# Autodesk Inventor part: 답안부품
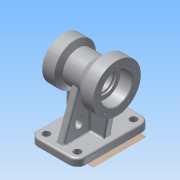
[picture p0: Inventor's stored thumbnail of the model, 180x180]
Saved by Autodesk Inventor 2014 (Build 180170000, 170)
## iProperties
Created: 2015-08
Part Number: 답안부품
Material: 알루미늄 6061
Document SubType Name: Modeling
Designer: sda20
Density: 2.71 g/cm^3
Appearance: 알루미늄 - 평지
Mass: 1067.5 g
Surface Area: 774.349 cm^2
Volume: 393.91 cm^3
Author: sda20
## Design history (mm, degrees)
sketch "스케치9"
  geometry: C1 r 26 at (0, 0); 1 further point
  constraints: 1 centre point, 1 coincident
  dimensions: "d93" = 52 diameter of C1
extrude "돌출4" new body sketch "스케치9" stored distance "d94" = 50; taper "d95" = 0 deg
sketch "스케치10"
  geometry: C1 r 26 at (0, 0) reference; C2 r 35 at (0, 0)
  constraints: 1 centre point, 1 coincident
  dimensions: "d96" = 70 diameter of C2
extrude "돌출5" join sketch "스케치10" distance "d97" = 20; taper "d98" = 0 deg
sketch "스케치11"
  geometry: C1 r 26 at (0, 0) reference; C2 r 40 at (0, 0)
  constraints: 1 centre point, 1 coincident
  dimensions: "d99" = 80 diameter of C2
extrude "돌출6" join sketch "스케치11" distance "d100" = 20; taper "d101" = 0 deg
sketch "스케치12"
  geometry: L1 (-35, 25)-(35, 25) reference; L2 (35, 45)-(-35, 45) reference; L3 (0, 45)-(0, -45); L4 (-40, -45)-(40, -45) reference; L5 (35, 25)-(26, 19.804); L6 (26, -25)-(26, 25) reference; L7 (40, -25)-(-40, -25) reference; L8 (40, -25)-(26, -8.315); 1 further point
  constraints: 7 end point, 2 midpoint, 2 point on line, 1 perpendicular
  dimensions: "d102" = 60 deg angle of L6 L5; "d103" = 40 deg angle of L6 L8
revolve "회전3" sketch "스케치12" stored, may be unused: angle "d104" = 90 deg
node "작업 평면4"
sketch "스케치13"
  geometry: L1 (61, 40)-(-61, 40); L2 (-61, 40)-(-61, -40); L3 (-61, -40)-(61, -40); L4 (61, -40)-(61, 40); L5 (61, 40)-(-61, -40); L6 (-61, 40)-(61, -40); 1 further point
  constraints: 12 end point, 2 midpoint, 2 parallel, 1 horizontal, 1 perpendicular
  dimensions: "d106" = 122 distance of L3.end L2.end; "d107" = 80 distance of L3.end L1.start
extrude "돌출7" join sketch "스케치13" distance "d108" = 12; taper "d109" = 0 deg
hole "구멍9" diameter "d122" = 52; stored, may be unused: countersink angle "d126" = 90 deg, drill point angle "d128" = 0 deg; dims "d120" = 10, "d121" = 10, "d123" = 6, "d124" = 4, "d125" = 2, "d127" = 20
hole "구멍10" diameter "d131" = 38; stored, may be unused: countersink angle "d135" = 90 deg, drill point angle "d137" = 0 deg; dims "d129" = 10, "d130" = 10, "d132" = 6, "d133" = 4, "d134" = 2, "d136" = 3
hole "구멍11" diameter "d140" = 40; stored, may be unused: countersink angle "d144" = 90 deg, drill point angle "d146" = 0 deg; dims "d138" = 10, "d139" = 10, "d141" = 6, "d142" = 4, "d143" = 2, "d145" = 17
hole "구멍12" diameter "d149" = 32; stored, may be unused: countersink angle "d153" = 90 deg, drill point angle "d155" = 0 deg; dims "d147" = 10, "d148" = 10, "d150" = 6, "d151" = 4, "d152" = 2, "d154" = 17
sketch "스케치18" dims "d156" = 54
  geometry: C1 r 20 at (0, 0) reference; C2 r 35 at (0, 0) reference; 2 further points
  constraints: 2 vertical alignment, 1 coincident, 2 other
hole "구멍13" sketch "스케치18" at (0, 27) diameter "d157" = 3.242; stored, may be unused: countersink angle "d161" = 90 deg, drill point angle "d163" = 118 deg; dims "d158" = 10, "d159" = 4, "d160" = 2, "d162" = 13
sketch "스케치19" dims "d167" = 66
  geometry: C1 r 26 at (0, 0) reference; C2 r 40 at (0, 0) reference; 2 further points
  constraints: 2 vertical alignment, 1 coincident, 2 other
hole "구멍14" sketch "스케치19" at (0, 33) diameter "d168" = 3.242; stored, may be unused: countersink angle "d172" = 90 deg, drill point angle "d174" = 118 deg; dims "d169" = 10, "d170" = 4, "d171" = 2, "d173" = 13
sketch "스케치23"
  geometry: L1 (25.091, -6.815)-(51, -78); L2 (-61, -78)-(61, -78) reference; L3 (61, -90)-(61, -78) reference; L4 (61, -78)-(-61, -78) reference; L5 (0, -78)-(0, -26); L6 (0, -78)-(51, -78); A1 r 26 centre (0, 0) between (0, -26) and (25.091, -6.815); 1 further point
  constraints: 6 end point, 2 point on circle, 1 centre point, 1 coincident, 1 collinear, 1 midpoint, 1 perpendicular, 1 point on line
  dimensions: "d185" = 10 distance from line of L3 L1.end; "d186" = 70 deg angle of L2 L1; "d192" = 26 radius of A1
extrude "돌출9" join sketch "스케치23" stored distance "d193" = 12; taper "d194" = 0 deg
sketch "스케치24"
  geometry: L1 (-35, 25)-(-35, 45) reference; L2 (-35, 25)-(-26, 19.804) reference; L3 (-26, -8.315)-(-26, 19.804) reference; L4 (-26, -8.315)-(-40, -25) reference; L5 (-40, -25)-(-40, -45) reference; L6 (-78, -40)-(-78, 40) reference; L7 (-40, -36.7)-(-78, -30); L8 (-90, -40)-(-78, -40) reference; L9 (-35, 35)-(-78, 35); 1 further point
  constraints: 4 end point, 3 point on line, 1 midpoint, 1 perpendicular
  dimensions: "d195" = 10 distance from line of L8 L7.end; "d196" = 80 deg angle of L6 L7
extrude "돌출10" join sketch "스케치24" stored distance "d197" = 12; taper "d198" = 0 deg
sketch "스케치25"
  geometry: 2 further points
  dimensions: "d199" = 47 horizontal distance of point (0, 0) point (-47, 26); "d200" = 26 vertical distance of point (0, 0) point (-47, 26)
hole "구멍15" sketch "스케치25" at (-47, 26) diameter "d201" = 12; stored, may be unused: countersink angle "d205" = 90 deg, drill point angle "d207" = 0 deg; dims "d202" = 12, "d203" = 4, "d204" = 2, "d206" = 13
sketch "스케치26"
  geometry: L1 (-6, -78)-(-51, -78) reference; L2 (-18, -54)-(-18, -60); L3 (-30, -54)-(-30, -60); A1 r 26 centre (0, 0) between (-25.091, -6.815) and (0, -26) reference; A2 r 6 centre (-24, -60) between (-30, -60) and (-18, -60); A3 r 6 centre (-24, -54) between (-18, -54) and (-30, -54); 2 further points
  constraints: 6 point on circle, 4 end point, 3 tangent, 3 vertical alignment, 2 centre point, 1 parallel
  dimensions: "d210" = 12 diameter of A2; "d211" = 18 distance from line of L1 A2.centre; "d212" = 24 horizontal distance of A1.centre A2.centre; "d213" = 12 diameter of A3; "d214" = 18 distance of point (-24, -48) point (-24, -66)
extrude "돌출11" cut sketch "스케치26" stored distance "d215" = 0; taper "d216" = 0 deg
fillet "모깎기1" dims "d217" = 0.3
fillet "모깎기2" dims "d218" = 5
fillet "모깎기3" dims "d219" = 0.3
fillet "모깎기4" dims "d220" = 14
fillet "모깎기5" dims "d221" = 3
sketch "스케치28"
  geometry: L1 (-40, -78)-(-26, -78) reference; L2 (-40, -78)-(-40, -90) reference; L3 (-35, -35)-(-35, -75) reference; 2 further points
  constraints: 1 other
  dimensions: "d222" = 24 distance from line of L1 point (-19, -54); "d224" = 16 distance from line of L3 point (-19, -54)
feature "엠보싱1" sketch "스케치28" dims "d225" = 0.5, "d226" = 0
chamfer "모따기1" distance "d227" = 1; stored, may be unused: second distance "d228" = 2, angle "d229" = 45 deg
fillet "모깎기6" dims "d230" = 3
fillet "모깎기7" dims "d231" = 3
node "솔리드2"
pattern_circular "원형 패턴1" dims angle "d165" = 360 deg
pattern_circular "원형 패턴2" dims angle "d176" = 360 deg
mirror "대칭2"
mirror "대칭3"
mirror "대칭4"
mirror "대칭5"
